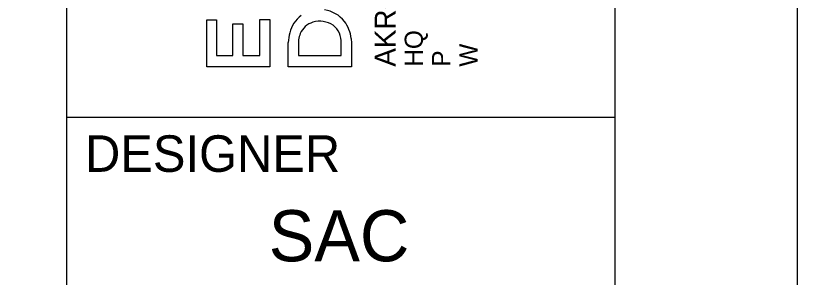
# Model space of a CAD drawing. Extents: x -0.2 to 34, y 0 to 22.
# Drawn here: x 31.86 to 34, y 2.061 to 2.778 of the extents above; entities that cross this region are included whole.
import ezdxf

# ---------------------------------------------------------------- set-up
doc = ezdxf.new("R2010")
doc.units = 0
for name, color, linetype in [('SH_Border', 7, 'Continuous'), ('SH_Cut_Line', 7, 'Continuous'), ('SH_Data', 7, 'Continuous')]:
    doc.layers.add(name, color=color, linetype=linetype)

msp = doc.modelspace()

# ---------------------------------------------------------------- linework, layer by layer
at = {"layer": 'SH_Border'}
for p, q in [((32.383, 2.6379), (32.383, 2.766)), ((32.383, 2.766), (32.4101, 2.766)), ((32.4101, 2.766), (32.4101, 2.6683)), ((32.5286, 2.6683), (32.5286, 2.7672)), ((32.5286, 2.7672), (32.5557, 2.7672)), ((32.5557, 2.7672), (32.5557, 2.6379)), ((32.455, 2.6683), (32.455, 2.7549)), ((32.455, 2.7549), (32.4822, 2.7549)), ((32.4822, 2.7549), (32.4822, 2.6683)), ((32.6064, 2.638), (32.6064, 2.704)), ((32.6347, 2.7118), (32.6341, 2.7023)), ((32.6341, 2.7023), (32.6341, 2.6684)), ((32.7515, 2.6683), (32.7515, 2.7024)), ((32.7785, 2.715), (32.7792, 2.7021)), ((32.7792, 2.7021), (32.7792, 2.638)), ((32.4101, 2.6683), (32.455, 2.6683)), ((32.4822, 2.6683), (32.5286, 2.6683)), ((32.6341, 2.6684), (32.7515, 2.6683)), ((32.5557, 2.6379), (32.383, 2.6379)), ((32.7792, 2.638), (32.6064, 2.638))]:
    msp.add_line(p, q, dxfattribs=at)
msp.add_lwpolyline([(32.383, 2.6379), (32.383, 2.766), (32.4101, 2.766), (32.4101, 2.6683), (32.455, 2.6683), (32.455, 2.7549), (32.4822, 2.7549), (32.4822, 2.6683), (32.5286, 2.6683), (32.5286, 2.7672), (32.5557, 2.7672), (32.5557, 2.6379)], close=True, dxfattribs=at)
for points in [[(32.7785, 2.715), (32.7792, 2.7021), (32.7792, 2.638), (32.6064, 2.638)], [(32.6064, 2.638), (32.6064, 2.704)], [(32.6347, 2.7118), (32.6341, 2.7023), (32.6341, 2.6684), (32.7515, 2.6683), (32.7515, 2.7024)]]:
    msp.add_lwpolyline(points, dxfattribs=at)
for centre, radius, start, end in [((32.6946, 2.7113), 0.0827, 37.8521, 82.402), ((32.6946, 2.7113), 0.0827, 37.8521, 82.402), ((32.6939, 2.7089), 0.0865, 127.2362, 165.148), ((32.6939, 2.7089), 0.0865, 127.2362, 165.148), ((32.6928, 2.6986), 0.0639, 55.6727, 107.2093), ((32.6928, 2.6986), 0.0639, 55.6727, 107.2093), ((32.6859, 2.7057), 0.0931, 5.7333, 37.304), ((32.6859, 2.7057), 0.0931, 5.7333, 37.304), ((32.6889, 2.7078), 0.054, 106.1881, 157.3861), ((32.6889, 2.7078), 0.054, 106.1881, 157.3861), ((32.6929, 2.705), 0.0587, 357.4662, 52.2665), ((32.6929, 2.705), 0.0587, 357.4662, 52.2665), ((32.7143, 2.7028), 0.1078, 164.7861, 179.3704), ((32.7143, 2.7028), 0.1078, 164.7861, 179.3704), ((32.6983, 2.7039), 0.0641, 157.3571, 172.9275), ((32.6983, 2.7039), 0.0641, 157.3571, 172.9275)]:
    msp.add_arc(centre, radius, start, end, dxfattribs=at)
at = {"layer": 'SH_Cut_Line'}
msp.add_lwpolyline([(0, 0), (34, 0), (34, 22), (0, 22)], close=True, dxfattribs=at)
at = {"layer": 'SH_Data'}
for p, q in [((32, 0.5), (32, 21.5)), ((32, 2.5), (33.5, 2.5))]:
    msp.add_line(p, q, dxfattribs=at)
msp.add_lwpolyline([(1.5, 21.5), (33.5, 21.5), (33.5, 0.5), (1.5, 0.5)], close=True, dxfattribs=at)

# ---------------------------------------------------------------- texts
at = {"layer": 'SH_Border'}
for s, height, p in [('AKRON / CLEVELAND / COLUMBUS', 0.056969, (32.9001, 2.638)), ('HQ ', 0.04985, (32.9749, 2.638)), ('W', 0.0498, (33.1244, 2.638)), ('P', 0.0498, (33.0497, 2.638))]:
    msp.add_text(s, height=height, rotation=90, dxfattribs=at).set_placement(p)
for s, height, p in [('DESIGNER', 0.1, (32.05, 2.35)), ('SAC', 0.14, (32.5528, 2.105))]:
    msp.add_text(s, height=height, dxfattribs=at).set_placement(p)

doc.saveas('drawing.dxf')
